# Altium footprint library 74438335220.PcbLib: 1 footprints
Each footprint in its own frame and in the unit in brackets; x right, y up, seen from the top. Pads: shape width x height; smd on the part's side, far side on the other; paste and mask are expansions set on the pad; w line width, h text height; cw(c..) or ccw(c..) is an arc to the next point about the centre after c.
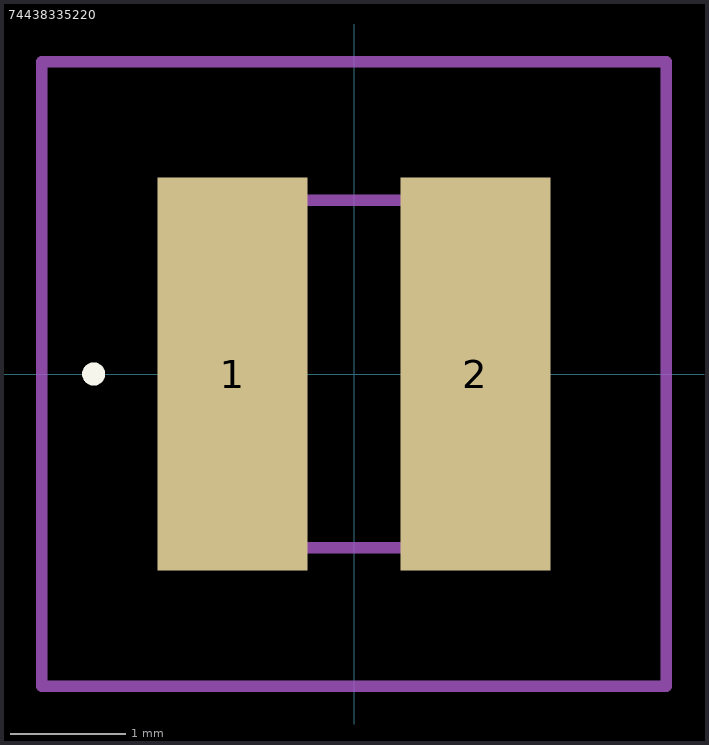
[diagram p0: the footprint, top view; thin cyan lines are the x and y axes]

## 74438335220 [mm]
pads (2):
  rect 1.3x3.4 smd: 1(-1.05,0) 2(1.05,0)
Top Overlay:
  lines w0.1: -2.3,0 cw(c-2.25,0) -2.2,0 ; -2.3,0 -2.3,0 ; -2.3,0 ccw(c-2.25,0) -2.2,0 ; -2.2,0 -2.2,0
Mechanical 15:
  lines w0.1: -1.5,-1.5 1.5,-1.5 1.5,1.5 -1.5,1.5 -1.5,-1.5
Mechanical 20:
  lines w0.1: -2.7,-2.7 2.7,-2.7 2.7,2.7 -2.7,2.7 -2.7,-2.7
